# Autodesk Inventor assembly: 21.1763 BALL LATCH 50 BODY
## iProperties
Created: 2007-07
Part Number: 21.1763 BALL LATCH 50 BODY
Document SubType Name: Assembly
Designer: Andy Moles
Author: Andy Moles
